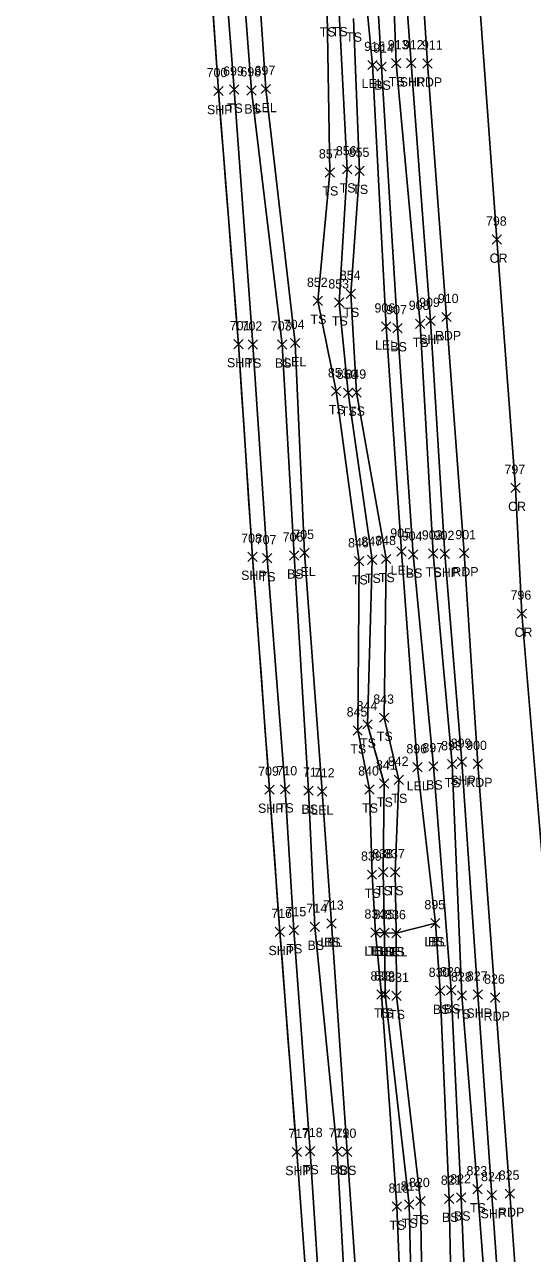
# Model space of a CAD drawing. Extents: x 1650221 to 1650634, y 244606 to 249996.
# Drawn here: x 1650345.8 to 1650455.2, y 244867.1 to 245132.2 of the extents above; entities that cross this region are included whole.
import ezdxf

# ---------------------------------------------------------------- set-up
doc = ezdxf.new("R2010")
doc.units = 0
for name, color, linetype in [('L_A', 7, 'Continuous'), ('L_I', 7, 'Continuous'), ('L_TIC', 7, 'Continuous'), ('LARO', 7, 'Continuous'), ('LELB', 7, 'Continuous'), ('LSOGP', 7, 'Continuous'), ('P_A', 7, 'Continuous'), ('P_I', 7, 'Continuous'), ('P_TIC', 7, 'Continuous'), ('PET', 7, 'Continuous'), ('PRC', 7, 'Continuous'), ('PSP', 7, 'Continuous')]:
    doc.layers.add(name, color=color, linetype=linetype)

msp = doc.modelspace()

# ---------------------------------------------------------------- linework, layer by layer
at = {"layer": 'L_TIC'}
for points in [[(1650419.77, 245122.48), (1650421.77, 245124.48)], [(1650421.77, 245122.48), (1650419.77, 245124.48)], [(1650421.69, 245122.12), (1650423.69, 245124.12)], [(1650423.69, 245122.12), (1650421.69, 245124.12)], [(1650424.84, 245122.86), (1650426.84, 245124.86)], [(1650426.84, 245122.86), (1650424.84, 245124.86)], [(1650389.97, 245117.17), (1650391.97, 245119.17)], [(1650391.97, 245117.17), (1650389.97, 245119.17)], [(1650393.69, 245117), (1650395.69, 245119)], [(1650395.69, 245117), (1650393.69, 245119)], [(1650396.75, 245117.3), (1650398.75, 245119.3)], [(1650398.75, 245117.3), (1650396.75, 245119.3)], [(1650410.56, 245099.31), (1650412.56, 245101.31)], [(1650412.56, 245099.31), (1650410.56, 245101.31)], [(1650414.28, 245099.97), (1650416.28, 245101.97)], [(1650416.28, 245099.97), (1650414.28, 245101.97)], [(1650416.99, 245099.65), (1650418.99, 245101.65)], [(1650418.99, 245099.65), (1650416.99, 245101.65)], [(1650415.07, 245073.13), (1650417.07, 245075.13)], [(1650417.07, 245073.13), (1650415.07, 245075.13)], [(1650407.99, 245071.61), (1650409.99, 245073.61)], [(1650409.99, 245071.61), (1650407.99, 245073.61)], [(1650412.6, 245071.27), (1650414.6, 245073.27)], [(1650414.6, 245071.27), (1650412.6, 245073.27)], [(1650430.01, 245066.65), (1650432.01, 245068.65)], [(1650432.01, 245066.65), (1650430.01, 245068.65)], [(1650422.68, 245066.08), (1650424.68, 245068.08)], [(1650424.68, 245066.08), (1650422.68, 245068.08)], [(1650425.15, 245065.7), (1650427.15, 245067.7)], [(1650427.15, 245065.7), (1650425.15, 245067.7)], [(1650393.99, 245062.19), (1650395.99, 245064.19)], [(1650395.99, 245062.19), (1650393.99, 245064.19)], [(1650400.29, 245062.19), (1650402.29, 245064.19)], [(1650402.29, 245062.19), (1650400.29, 245064.19)], [(1650403.08, 245062.51), (1650405.08, 245064.51)], [(1650405.08, 245062.51), (1650403.08, 245064.51)], [(1650411.94, 245052.12), (1650413.94, 245054.12)], [(1650413.94, 245052.12), (1650411.94, 245054.12)], [(1650414.5, 245051.76), (1650416.5, 245053.76)], [(1650416.5, 245051.76), (1650414.5, 245053.76)], [(1650416.3, 245051.81), (1650418.3, 245053.81)], [(1650418.3, 245051.81), (1650416.3, 245053.81)], [(1650397.03, 245016.1), (1650399.03, 245018.1)], [(1650399.03, 245016.1), (1650397.03, 245018.1)], [(1650402.89, 245016.69), (1650404.89, 245018.69)], [(1650404.89, 245016.69), (1650402.89, 245018.69)], [(1650405.12, 245017.23), (1650407.12, 245019.23)], [(1650407.12, 245017.23), (1650405.12, 245019.23)], [(1650426.02, 245017.52), (1650428.02, 245019.52)], [(1650428.02, 245017.52), (1650426.02, 245019.52)], [(1650428.49, 245016.89), (1650430.49, 245018.89)], [(1650430.49, 245016.89), (1650428.49, 245018.89)], [(1650432.82, 245017.12), (1650434.82, 245019.12)], [(1650434.82, 245017.12), (1650432.82, 245019.12)], [(1650416.91, 245015.43), (1650418.91, 245017.43)], [(1650418.91, 245015.43), (1650416.91, 245017.43)], [(1650419.71, 245015.76), (1650421.71, 245017.76)], [(1650421.71, 245015.76), (1650419.71, 245017.76)], [(1650422.71, 245015.93), (1650424.71, 245017.93)], [(1650424.71, 245015.93), (1650422.71, 245017.93)], [(1650422.28, 244981.7), (1650424.28, 244983.7)], [(1650424.28, 244981.7), (1650422.28, 244983.7)], [(1650416.56, 244978.95), (1650418.56, 244980.95)], [(1650418.56, 244978.95), (1650416.56, 244980.95)], [(1650418.67, 244980.26), (1650420.67, 244982.26)], [(1650420.67, 244980.26), (1650418.67, 244982.26)], [(1650429.48, 244971), (1650431.48, 244973)], [(1650431.48, 244971), (1650429.48, 244973)], [(1650432.87, 244971.21), (1650434.87, 244973.21)], [(1650434.87, 244971.21), (1650432.87, 244973.21)], [(1650436.91, 244971.67), (1650438.91, 244973.67)], [(1650438.91, 244971.67), (1650436.91, 244973.67)], [(1650425.44, 244968.3), (1650427.44, 244970.3)], [(1650427.44, 244968.3), (1650425.44, 244970.3)], [(1650400.94, 244966.25), (1650402.94, 244968.25)], [(1650402.94, 244966.25), (1650400.94, 244968.25)], [(1650405.99, 244965.96), (1650407.99, 244967.96)], [(1650407.99, 244965.96), (1650405.99, 244967.96)], [(1650408.93, 244965.8), (1650410.93, 244967.8)], [(1650410.93, 244965.8), (1650408.93, 244967.8)], [(1650419.12, 244966.21), (1650421.12, 244968.21)], [(1650421.12, 244966.21), (1650419.12, 244968.21)], [(1650422.3, 244967.5), (1650424.3, 244969.5)], [(1650424.3, 244967.5), (1650422.3, 244969.5)], [(1650419.65, 244947.84), (1650421.65, 244949.84)], [(1650421.65, 244947.84), (1650419.65, 244949.84)], [(1650422.08, 244948.37), (1650424.08, 244950.37)], [(1650424.08, 244948.37), (1650422.08, 244950.37)], [(1650424.63, 244948.38), (1650426.63, 244950.38)], [(1650426.63, 244948.38), (1650424.63, 244950.38)], [(1650407.31, 244936.61), (1650409.31, 244938.61)], [(1650409.31, 244936.61), (1650407.31, 244938.61)], [(1650410.89, 244937.28), (1650412.89, 244939.28)], [(1650412.89, 244937.28), (1650410.89, 244939.28)], [(1650410.89, 244937.28), (1650412.89, 244939.28)], [(1650412.89, 244937.28), (1650410.89, 244939.28)], [(1650433.3, 244937.37), (1650435.3, 244939.37)], [(1650435.3, 244937.37), (1650433.3, 244939.37)], [(1650433.3, 244937.37), (1650435.3, 244939.37)], [(1650435.3, 244937.37), (1650433.3, 244939.37)], [(1650402.81, 244935.86), (1650404.81, 244937.86)], [(1650404.81, 244935.86), (1650402.81, 244937.86)], [(1650420.38, 244935.36), (1650422.38, 244937.36)], [(1650422.38, 244935.36), (1650420.38, 244937.36)], [(1650420.38, 244935.36), (1650422.38, 244937.36)], [(1650422.38, 244935.36), (1650420.38, 244937.36)], [(1650422.35, 244935.27), (1650424.35, 244937.27)], [(1650424.35, 244935.27), (1650422.35, 244937.27)], [(1650422.35, 244935.27), (1650424.35, 244937.27)], [(1650424.35, 244935.27), (1650422.35, 244937.27)], [(1650424.89, 244935.22), (1650426.89, 244937.22)], [(1650426.89, 244935.22), (1650424.89, 244937.22)], [(1650424.89, 244935.22), (1650426.89, 244937.22)], [(1650426.89, 244935.22), (1650424.89, 244937.22)], [(1650421.68, 244921.99), (1650423.68, 244923.99)], [(1650423.68, 244921.99), (1650421.68, 244923.99)], [(1650422.48, 244922.01), (1650424.48, 244924.01)], [(1650424.48, 244922.01), (1650422.48, 244924.01)], [(1650424.94, 244921.68), (1650426.94, 244923.68)], [(1650426.94, 244921.68), (1650424.94, 244923.68)], [(1650434.31, 244922.78), (1650436.31, 244924.78)], [(1650436.31, 244922.78), (1650434.31, 244924.78)], [(1650436.68, 244922.9), (1650438.68, 244924.9)], [(1650438.68, 244922.9), (1650436.68, 244924.9)], [(1650439.04, 244921.8), (1650441.04, 244923.8)], [(1650441.04, 244921.8), (1650439.04, 244923.8)], [(1650406.34, 244888.23), (1650408.34, 244890.23)], [(1650408.34, 244888.23), (1650406.34, 244890.23)], [(1650412.12, 244888.16), (1650414.12, 244890.16)], [(1650414.12, 244888.16), (1650412.12, 244890.16)], [(1650414.27, 244888.08), (1650416.27, 244890.08)], [(1650416.27, 244888.08), (1650414.27, 244890.08)], [(1650438.87, 244878.23), (1650440.87, 244880.23)], [(1650440.87, 244878.23), (1650438.87, 244880.23)], [(1650442.38, 244879.99), (1650444.38, 244881.99)], [(1650444.38, 244879.99), (1650442.38, 244881.99)], [(1650425.01, 244876.24), (1650427.01, 244878.24)], [(1650427.01, 244876.24), (1650425.01, 244878.24)], [(1650427.64, 244876.68), (1650429.64, 244878.68)], [(1650429.64, 244876.68), (1650427.64, 244878.68)], [(1650430.08, 244877.45), (1650432.08, 244879.45)], [(1650432.08, 244877.45), (1650430.08, 244879.45)], [(1650436.28, 244877.95), (1650438.28, 244879.95)], [(1650438.28, 244877.95), (1650436.28, 244879.95)]]:
    msp.add_lwpolyline(points, dxfattribs=at)
at = {"layer": 'LARO'}
for points in [[(1650421.38, 244936.36), (1650423.35, 244936.27), (1650425.89, 244936.22), (1650434.3, 244938.37), (1650430.48, 244972), (1650427.02, 245018.52), (1650423.68, 245067.08), (1650420.77, 245123.48), (1650416.16, 245170.75), (1650416.29, 245170.75), (1650411.97, 245219.01), (1650407.36, 245272.17), (1650403.92, 245328.57), (1650398.22, 245379.76), (1650393.14, 245434.28), (1650390.04, 245478.89), (1650387.05, 245523.12), (1650386.02, 245551.2)], [(1650370.23, 245505.43), (1650373.27, 245470.75), (1650376.08, 245419.34), (1650380.61, 245367.82), (1650383.54, 245316.3), (1650388.29, 245270.51), (1650390.54, 245221.61), (1650394.38, 245168.62), (1650397.75, 245118.3), (1650404.08, 245063.51), (1650406.12, 245018.23), (1650409.93, 244966.8), (1650411.89, 244938.28)]]:
    msp.add_lwpolyline(points, dxfattribs=at)
at = {"layer": 'LELB'}
for points in [[(1650349.13, 245703.09), (1650351.39, 245660.59), (1650355.99, 245608.05), (1650358.47, 245560.96), (1650362.91, 245508.7), (1650365.76, 245471.06), (1650369.41, 245419.53), (1650373.04, 245367.18), (1650376.89, 245316.29), (1650379.01, 245269.77), (1650383.48, 245220.96), (1650387.1, 245168.26), (1650390.97, 245118.17), (1650394.99, 245063.19), (1650398.03, 245017.1), (1650401.94, 244967.25), (1650403.81, 244936.86), (1650407.34, 244889.23), (1650410.84, 244834.73), (1650414.52, 244785.95), (1650419.34, 244732.83), (1650422.93, 244682.99), (1650426.36, 244632.18), (1650427.51, 244611.7)], [(1650355.71, 245703.22), (1650358.45, 245660.47), (1650361.92, 245609.02), (1650362.95, 245561.76), (1650366.97, 245508.68), (1650370.97, 245471.38), (1650374.07, 245419.38), (1650376.64, 245367.03), (1650382.18, 245316.08), (1650385.68, 245270.43), (1650388.77, 245221.07), (1650390.77, 245168.69), (1650394.69, 245118), (1650401.29, 245063.19), (1650403.89, 245017.69), (1650406.99, 244966.96), (1650408.31, 244937.61), (1650413.12, 244889.16), (1650416.09, 244835.73), (1650420.51, 244786.1), (1650423.8, 244733.3), (1650426.51, 244682.57), (1650434.12, 244632.73), (1650437.01, 244612.78)], [(1650458.26, 244631.23), (1650456.79, 244671.65), (1650452.78, 244720.4), (1650448.37, 244766.08), (1650444.9, 244801.26), (1650441.62, 244837.94), (1650439.87, 244879.23), (1650437.68, 244923.9), (1650433.87, 244972.21), (1650429.49, 245017.89), (1650426.15, 245066.7), (1650422.69, 245123.12), (1650419.86, 245170.84), (1650416.52, 245219.13), (1650411.95, 245271.56), (1650407.71, 245328.35), (1650401.82, 245379.92), (1650396.45, 245433.97), (1650394.84, 245478.56), (1650392.49, 245522.5), (1650389.35, 245551.29), (1650385.12, 245588.75), (1650380.77, 245632.36), (1650373.15, 245685.41)], [(1650462.3, 244631.92), (1650459.1, 244671.43), (1650455.6, 244720.68), (1650451.8, 244765.92), (1650449.21, 244801.88), (1650446.61, 244838.72), (1650443.38, 244880.99), (1650440.04, 244922.8), (1650437.91, 244972.67), (1650433.82, 245018.12), (1650431.01, 245067.65), (1650425.84, 245123.86), (1650424.05, 245171.63), (1650419.6, 245218.92), (1650416.04, 245272.16), (1650411.76, 245328.09), (1650406.63, 245381.03), (1650402.95, 245434.27), (1650400.25, 245479.81), (1650396.41, 245522.79), (1650395.43, 245551.92), (1650392.44, 245589.61), (1650388.27, 245633.5), (1650384.04, 245685.26)], [(1650438.88, 244749.14), (1650437.59, 244767.7), (1650432.8, 244801.89), (1650429.64, 244835.41), (1650428.64, 244877.68), (1650423.48, 244923.01), (1650423.35, 244936.27), (1650423.08, 244949.37), (1650423.3, 244968.5), (1650419.67, 244981.26), (1650420.71, 245016.76), (1650415.5, 245052.76), (1650413.6, 245072.27), (1650415.28, 245100.97), (1650413.57, 245134.68), (1650410.33, 245167.49), (1650406.45, 245196.84), (1650403.51, 245234.02), (1650401.64, 245258.7)], [(1650434.33, 244767.21), (1650430.39, 244802.16), (1650427.74, 244835.35), (1650426.01, 244877.24), (1650422.68, 244922.99), (1650421.38, 244936.36), (1650420.65, 244948.84), (1650420.12, 244967.21), (1650417.56, 244979.95), (1650417.91, 245016.43), (1650412.94, 245053.12), (1650408.99, 245072.61), (1650411.56, 245100.31), (1650410.98, 245134.62)], [(1650447.97, 244696.01), (1650442.83, 244719.93), (1650439.86, 244767.03), (1650436, 244801.8), (1650431.85, 244835.44), (1650431.08, 244878.45), (1650425.94, 244922.68), (1650425.89, 244936.22), (1650425.63, 244949.38), (1650426.44, 244969.3), (1650423.28, 244982.7), (1650423.71, 245016.93), (1650417.3, 245052.81), (1650416.07, 245074.13), (1650417.99, 245100.65), (1650416.66, 245133.49)], [(1650411.89, 244938.28), (1650415.27, 244889.08), (1650419.02, 244835.91), (1650424.03, 244784.72), (1650426.78, 244733.92), (1650430.2, 244682.93), (1650438.75, 244635.57), (1650441.06, 244623.77), (1650451.56, 244623.37), (1650454.31, 244633.1), (1650454.05, 244671.95), (1650450.18, 244720.54), (1650445.7, 244766.1), (1650441.52, 244801.17), (1650438.17, 244837.49), (1650437.28, 244878.95), (1650435.31, 244923.78), (1650434.3, 244938.37)]]:
    msp.add_lwpolyline(points, dxfattribs=at)
at = {"layer": 'LSOGP'}
msp.add_lwpolyline([(1650386.24, 245136.72), (1650386.67, 245130.43), (1650387.11, 245124.14), (1650387.54, 245117.86), (1650388.08, 245111.03), (1650388.62, 245104.21), (1650389.16, 245097.38), (1650389.7, 245090.56), (1650390.24, 245083.73), (1650390.78, 245076.91), (1650391.31, 245070.08), (1650391.85, 245063.26), (1650392.23, 245057.53), (1650392.62, 245051.8), (1650393, 245046.07), (1650393.38, 245040.34), (1650393.76, 245034.61), (1650394.14, 245028.88), (1650394.52, 245023.15), (1650394.9, 245017.42), (1650395.36, 245011.14), (1650395.82, 245004.86), (1650396.27, 244998.58), (1650396.73, 244992.29), (1650397.19, 244986.01), (1650397.64, 244979.73), (1650398.1, 244973.45), (1650398.56, 244967.17), (1650399.12, 244959.5), (1650399.68, 244951.83), (1650400.24, 244944.16), (1650400.8, 244936.49), (1650401.26, 244930.56), (1650401.71, 244924.62), (1650402.16, 244918.69), (1650402.61, 244912.75), (1650403.06, 244906.82), (1650403.52, 244900.88), (1650403.97, 244894.95), (1650404.42, 244889.02), (1650404.93, 244882.13), (1650405.43, 244875.25), (1650405.94, 244868.37), (1650406.44, 244861.49)], dxfattribs=at)
at = {"layer": 'P_TIC'}
for points in [[(1650428.09, 245122.84), (1650430.09, 245124.84)], [(1650430.09, 245122.84), (1650428.09, 245124.84)], [(1650431.63, 245122.79), (1650433.63, 245124.79)], [(1650433.63, 245122.79), (1650431.63, 245124.79)], [(1650386.54, 245116.86), (1650388.54, 245118.86)], [(1650388.54, 245116.86), (1650386.54, 245118.86)], [(1650446.57, 245084.81), (1650448.57, 245086.81)], [(1650448.57, 245084.81), (1650446.57, 245086.81)], [(1650432.26, 245067.28), (1650434.26, 245069.28)], [(1650434.26, 245067.28), (1650432.26, 245069.28)], [(1650435.73, 245068.12), (1650437.73, 245070.12)], [(1650437.73, 245068.12), (1650435.73, 245070.12)], [(1650390.85, 245062.26), (1650392.85, 245064.26)], [(1650392.85, 245062.26), (1650390.85, 245064.26)], [(1650450.55, 245031.27), (1650452.55, 245033.27)], [(1650452.55, 245031.27), (1650450.55, 245033.27)], [(1650393.9, 245016.42), (1650395.9, 245018.42)], [(1650395.9, 245016.42), (1650393.9, 245018.42)], [(1650435.37, 245017.02), (1650437.37, 245019.02)], [(1650437.37, 245017.02), (1650435.37, 245019.02)], [(1650439.49, 245017.18), (1650441.49, 245019.18)], [(1650441.49, 245017.18), (1650439.49, 245019.18)], [(1650451.93, 245004.14), (1650453.93, 245006.14)], [(1650453.93, 245004.14), (1650451.93, 245006.14)], [(1650438.98, 244972.19), (1650440.98, 244974.19)], [(1650440.98, 244972.19), (1650438.98, 244974.19)], [(1650442.48, 244971.73), (1650444.48, 244973.73)], [(1650444.48, 244971.73), (1650442.48, 244973.73)], [(1650397.56, 244966.17), (1650399.56, 244968.17)], [(1650399.56, 244966.17), (1650397.56, 244968.17)], [(1650399.8, 244935.49), (1650401.8, 244937.49)], [(1650401.8, 244935.49), (1650399.8, 244937.49)], [(1650442.46, 244921.98), (1650444.46, 244923.98)], [(1650444.46, 244921.98), (1650442.46, 244923.98)], [(1650446.22, 244921.32), (1650448.22, 244923.32)], [(1650448.22, 244921.32), (1650446.22, 244923.32)], [(1650403.42, 244888.02), (1650405.42, 244890.02)], [(1650405.42, 244888.02), (1650403.42, 244890.02)], [(1650445.5, 244878.72), (1650447.5, 244880.72)], [(1650447.5, 244878.72), (1650445.5, 244880.72)], [(1650449.33, 244879.04), (1650451.33, 244881.04)], [(1650451.33, 244879.04), (1650449.33, 244881.04)]]:
    msp.add_lwpolyline(points, dxfattribs=at)
at = {"layer": 'PET'}
msp.add_lwpolyline([(1650468.61, 244633.66), (1650465.16, 244679.18), (1650461.18, 244730.39), (1650457.78, 244777.29), (1650455.76, 244806.01), (1650453.3, 244838.79), (1650450.33, 244880.04), (1650447.22, 244922.32), (1650443.48, 244972.73), (1650440.49, 245018.18), (1650436.73, 245069.12), (1650432.63, 245123.79), (1650429.44, 245172.68), (1650426.2, 245218.76), (1650422.12, 245272.82), (1650418.28, 245328.28), (1650414.28, 245381.59), (1650410.42, 245434.18), (1650407.03, 245480.26), (1650404.25, 245522.13), (1650401.81, 245552.98), (1650399.16, 245589.27), (1650395.97, 245634.45), (1650392.36, 245685.55)], dxfattribs=at)
at = {"layer": 'PRC'}
msp.add_lwpolyline([(1650480.45, 244632.95), (1650477.62, 244672.59), (1650473.75, 244722.56), (1650470.31, 244766.82), (1650467.4, 244803.77), (1650467.33, 244807.38), (1650463.88, 244858.27), (1650461.18, 244894.73), (1650457.56, 244949.95), (1650452.93, 245005.14), (1650451.55, 245032.27), (1650447.57, 245085.81), (1650443.28, 245144.22)], dxfattribs=at)
at = {"layer": 'PSP'}
for points in [[(1650345.78, 245703.18), (1650348.63, 245659.65), (1650352.24, 245608.27), (1650356.14, 245560.76), (1650359.83, 245508.67), (1650362.71, 245470.35), (1650366.37, 245419.55), (1650370.09, 245366.17), (1650373.73, 245316.16), (1650376.75, 245269.64), (1650380.21, 245220.67), (1650384.07, 245168.16), (1650387.54, 245117.86), (1650391.85, 245063.26), (1650394.9, 245017.42), (1650398.56, 244967.17), (1650400.8, 244936.49), (1650404.42, 244889.02), (1650408.47, 244833.97), (1650411.77, 244786.13), (1650415.79, 244732.16), (1650419.27, 244682.87), (1650423.02, 244632.43), (1650424.78, 244611.26)], [(1650464.84, 244632.07), (1650461.81, 244671.31), (1650457.94, 244720.75), (1650454.77, 244765.54), (1650451.99, 244802.46), (1650449.34, 244838.71), (1650446.5, 244879.72), (1650443.46, 244922.98), (1650439.98, 244973.19), (1650436.37, 245018.02), (1650433.26, 245068.28), (1650429.09, 245123.84), (1650425.59, 245171.99), (1650422.33, 245218.99), (1650418.38, 245272.19), (1650414.3, 245328), (1650410.4, 245381.3), (1650406.52, 245434.23), (1650403.48, 245480), (1650400.24, 245522.79), (1650398.25, 245552.46), (1650395.41, 245589.43), (1650392.23, 245633.8), (1650388.44, 245685.1)]]:
    msp.add_lwpolyline(points, dxfattribs=at)

# ---------------------------------------------------------------- texts
at = {"layer": 'L_A'}
for s, p in [('TS', (1650409.39, 245129.62)), ('TS', (1650411.98, 245129.68)), ('TS', (1650415.07, 245128.49)), ('LEL', (1650418.41, 245118.48)), ('BS', (1650421.13, 245118.12)), ('TS', (1650424.25, 245118.86)), ('TS', (1650389.38, 245113.17)), ('BS', (1650393.13, 245113)), ('LEL', (1650395.38, 245113.3)), ('TS', (1650413.68, 245095.97)), ('TS', (1650416.4, 245095.65)), ('TS', (1650409.97, 245095.31)), ('TS', (1650414.48, 245069.13)), ('TS', (1650407.4, 245067.61)), ('TS', (1650412.01, 245067.27)), ('LEL', (1650421.31, 245062.08)), ('BS', (1650424.59, 245061.7)), ('TS', (1650429.42, 245062.65)), ('LEL', (1650401.72, 245058.51)), ('TS', (1650393.4, 245058.19)), ('BS', (1650399.73, 245058.19)), ('TS', (1650411.35, 245048.12)), ('TS', (1650415.71, 245047.81)), ('TS', (1650413.91, 245047.76)), ('LEL', (1650424.66, 245013.52)), ('TS', (1650396.44, 245012.1)), ('BS', (1650402.33, 245012.69)), ('LEL', (1650403.76, 245013.23)), ('TS', (1650416.32, 245011.43)), ('TS', (1650419.12, 245011.76)), ('TS', (1650422.12, 245011.93)), ('BS', (1650427.93, 245012.89)), ('TS', (1650432.23, 245013.12)), ('TS', (1650418.08, 244976.26)), ('TS', (1650421.69, 244977.7)), ('TS', (1650415.97, 244974.95)), ('LEL', (1650428.12, 244967)), ('BS', (1650432.31, 244967.21)), ('TS', (1650436.32, 244967.67)), ('TS', (1650421.71, 244963.5)), ('TS', (1650424.84, 244964.3)), ('TS', (1650400.35, 244962.25)), ('BS', (1650405.43, 244961.96)), ('LEL', (1650407.56, 244961.8)), ('TS', (1650418.53, 244962.21)), ('TS', (1650419.06, 244943.84)), ('TS', (1650421.49, 244944.37)), ('TS', (1650424.04, 244944.38)), ('TS', (1650402.22, 244931.86)), ('BS', (1650406.75, 244932.61)), ('LEL', (1650409.52, 244933.28)), ('BS', (1650410.33, 244933.28)), ('LEL', (1650419.02, 244931.36)), ('TS', (1650419.79, 244931.36)), ('LEL', (1650420.98, 244931.27)), ('TS', (1650421.75, 244931.27)), ('LEL', (1650423.53, 244931.22)), ('TS', (1650424.3, 244931.22)), ('LEL', (1650431.94, 244933.37)), ('BS', (1650432.74, 244933.37)), ('TS', (1650421.09, 244917.99)), ('TS', (1650421.89, 244918.01)), ('BS', (1650433.76, 244918.78)), ('BS', (1650436.12, 244918.9)), ('TS', (1650424.34, 244917.68)), ('TS', (1650438.45, 244917.8)), ('TS', (1650405.75, 244884.23)), ('BS', (1650411.56, 244884.16)), ('BS', (1650413.71, 244884.08)), ('TS', (1650441.79, 244875.99)), ('TS', (1650429.49, 244873.45)), ('BS', (1650435.72, 244873.95)), ('BS', (1650438.31, 244874.23)), ('TS', (1650424.42, 244872.24)), ('TS', (1650427.05, 244872.68))]:
    msp.add_text(s, height=2, dxfattribs=at).set_placement(p)
at = {"layer": 'L_I'}
for s, p in [('915', (1650418.97, 245126.48)), ('914', (1650420.9, 245126.12)), ('913', (1650424.04, 245126.86)), ('699', (1650388.56, 245121.17)), ('698', (1650392.28, 245121)), ('697', (1650395.34, 245121.3)), ('856', (1650412.86, 245103.97)), ('855', (1650415.63, 245103.65)), ('857', (1650409.2, 245103.31)), ('854', (1650413.71, 245077.13)), ('852', (1650406.63, 245075.61)), ('853', (1650411.24, 245075.27)), ('906', (1650421.18, 245070.08)), ('907', (1650423.71, 245069.7)), ('908', (1650428.57, 245070.65)), ('704', (1650401.64, 245066.51)), ('702', (1650392.54, 245066.19)), ('703', (1650398.85, 245066.19)), ('851', (1650411.15, 245056.12)), ('850', (1650413.05, 245055.76)), ('849', (1650414.93, 245055.81)), ('905', (1650424.58, 245021.52)), ('707', (1650395.59, 245020.1)), ('706', (1650401.39, 245020.69)), ('705', (1650403.68, 245021.23)), ('846', (1650415.49, 245019.43)), ('847', (1650418.35, 245019.76)), ('848', (1650421.35, 245019.93)), ('904', (1650427.05, 245020.89)), ('903', (1650431.38, 245021.12)), ('844', (1650417.31, 244984.26)), ('843', (1650420.92, 244985.7)), ('845', (1650415.19, 244982.95)), ('896', (1650428.06, 244975)), ('897', (1650431.51, 244975.21)), ('898', (1650435.55, 244975.67)), ('841', (1650421.5, 244971.5)), ('842', (1650424.07, 244972.3)), ('710', (1650400.06, 244970.25)), ('711', (1650405.76, 244969.96)), ('712', (1650408.13, 244969.8)), ('840', (1650417.67, 244970.21)), ('838', (1650420.72, 244952.37)), ('837', (1650423.27, 244952.38)), ('839', (1650418.28, 244951.84)), ('715', (1650402.01, 244939.86)), ('714', (1650406.52, 244940.61)), ('713', (1650410.09, 244941.28)), ('713', (1650410.09, 244941.28)), ('834', (1650419.02, 244939.36)), ('834', (1650419.02, 244939.36)), ('835', (1650420.98, 244939.27)), ('835', (1650420.98, 244939.27)), ('836', (1650423.48, 244939.22)), ('836', (1650423.48, 244939.22)), ('895', (1650431.94, 244941.37)), ('895', (1650431.94, 244941.37)), ('833', (1650420.32, 244925.99)), ('832', (1650421.12, 244926.01)), ('830', (1650432.87, 244926.78)), ('829', (1650435.31, 244926.9)), ('831', (1650424.14, 244925.68)), ('828', (1650437.68, 244925.8)), ('718', (1650405.55, 244892.23)), ('719', (1650411.31, 244892.16)), ('720', (1650412.82, 244892.08)), ('823', (1650441.02, 244883.99)), ('820', (1650428.63, 244881.45)), ('821', (1650435.49, 244881.95)), ('822', (1650437.5, 244882.23)), ('818', (1650424.21, 244880.24)), ('819', (1650426.83, 244880.68))]:
    msp.add_text(s, height=2, dxfattribs=at).set_placement(p)
at = {"layer": 'P_A'}
for s, p in [('SHP', (1650426.63, 245118.84)), ('RDP', (1650430.12, 245118.79)), ('SHP', (1650385.08, 245112.86)), ('CR', (1650446, 245080.81)), ('RDP', (1650434.21, 245064.12)), ('SHP', (1650430.79, 245063.28)), ('SHP', (1650389.39, 245058.26)), ('CR', (1650449.98, 245027.27)), ('SHP', (1650392.44, 245012.42)), ('SHP', (1650433.91, 245013.02)), ('RDP', (1650437.97, 245013.18)), ('CR', (1650451.36, 245000.14)), ('SHP', (1650437.51, 244968.19)), ('RDP', (1650440.97, 244967.73)), ('SHP', (1650396.09, 244962.17)), ('SHP', (1650398.34, 244931.49)), ('SHP', (1650440.99, 244917.98)), ('RDP', (1650444.71, 244917.32)), ('SHP', (1650401.95, 244884.02)), ('SHP', (1650444.04, 244874.72)), ('RDP', (1650447.82, 244875.04))]:
    msp.add_text(s, height=2, dxfattribs=at).set_placement(p)
at = {"layer": 'P_I'}
for s, p in [('912', (1650427.3, 245126.84)), ('911', (1650431.41, 245126.79)), ('700', (1650385.01, 245120.86)), ('798', (1650445.21, 245088.81)), ('910', (1650434.84, 245072.12)), ('909', (1650430.81, 245071.28)), ('701', (1650389.98, 245066.26)), ('797', (1650449.19, 245035.27)), ('708', (1650392.46, 245020.42)), ('902', (1650433.93, 245021.02)), ('901', (1650438.61, 245021.18)), ('796', (1650450.51, 245008.14)), ('899', (1650437.61, 244976.19)), ('900', (1650440.95, 244975.73)), ('709', (1650396.11, 244970.17)), ('716', (1650398.95, 244939.49)), ('827', (1650441.09, 244925.98)), ('826', (1650444.81, 244925.32)), ('717', (1650402.62, 244892.02)), ('824', (1650444.14, 244882.72)), ('825', (1650447.97, 244883.04))]:
    msp.add_text(s, height=2, dxfattribs=at).set_placement(p)

doc.saveas('drawing.dxf')
